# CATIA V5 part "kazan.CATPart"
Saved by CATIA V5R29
Part number: kazan
Revision: HERHANG?
Definition: B??MEYEN
Nomenclature: kazan
Source: Unknown
Bounding box of the stored display mesh (mm): x -530.254 to 530.254, y -530.254 to 530.254, z -1560 to 0
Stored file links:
  C:\Users\제5강의실-27\Desktop\가치같이_내작업\kazan.CATPart
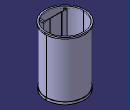
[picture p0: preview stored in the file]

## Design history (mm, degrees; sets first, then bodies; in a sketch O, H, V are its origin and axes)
Set1
  Sketch1 on face of Solid1, origin (0, 0, -1560), H (1, 0, 0), V (0, -1, 0)
    circle A1 centre (-446.4944, -55.075) radius 22.5
    reference projected arc E1 centre (-446.4944, -55.075) radius 22.5 from (-468.9944, -55.075) to (-423.9944, -55.075) ccw from edge [face of Solid1 | face of Solid1]
    circle A2 centre (386.9998, -233.0187) radius 11.5
    reference projected arc E2 centre (386.9998, -233.0187) radius 11.5 from (375.4998, -233.0187) to (398.4998, -233.0187) ccw from edge [face of Solid1 | face of Solid1]
    coincidence: A1 E1, E2 A2
Body1 "Kes-Ekstr?yon2" (main body)
  Solid1: solid without history
  Pad1: profile Sketch1, direction (0, 0, 1), length 45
